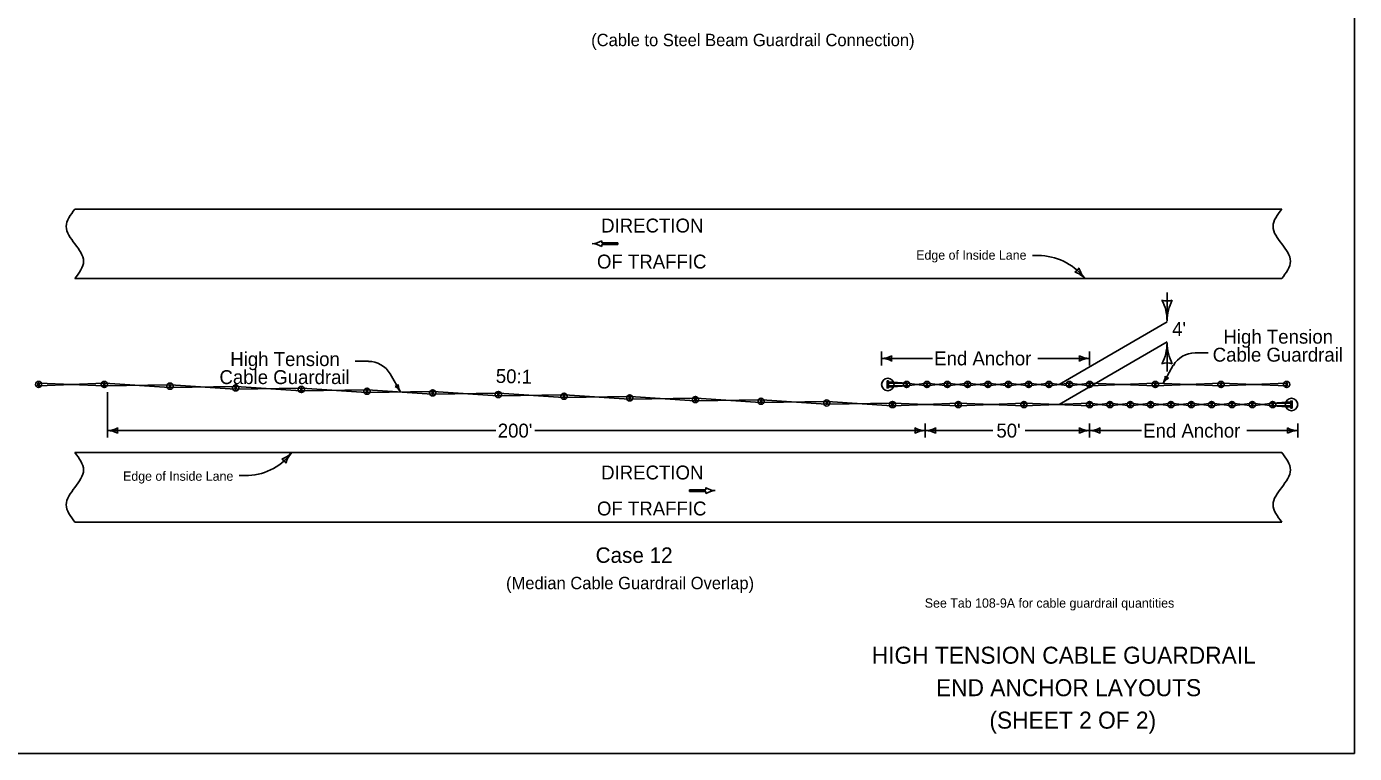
# Model space of a CAD drawing. Extents: x 10133 to 81668, y 7924 to 11018.
# Drawn here: x 15149 to 16868, y 7924 to 8864 of the extents above; entities that cross this region are included whole.
import ezdxf

# ---------------------------------------------------------------- set-up
doc = ezdxf.new("R2010")
doc.units = 0
for name, color, linetype in [('dsnCellElements', 7, 'Continuous'), ('dsnShadingGranular', 7, 'Continuous'), ('DsnShtRevisedText', 7, 'Continuous'), ('dsnStdDimension', 7, 'Continuous'), ('dsnTextTabulation', 7, 'Continuous'), ('Level 8', 7, 'Continuous'), ('SheetBorder', 7, 'Continuous')]:
    doc.layers.add(name, color=color, linetype=linetype)

msp = doc.modelspace()

# ---------------------------------------------------------------- linework, layer by layer
at = {"layer": 'dsnCellElements'}
for p, q in [((16263.5, 8404.9), (16288.6, 8403.1)), ((15248.7, 8403.1), (15165, 8399.7)), ((15248.7, 8399.7), (15165, 8403.1)), ((15250, 8399.7), (15333.7, 8400.9)), ((15250.1, 8403), (15333.7, 8397.5)), ((15335.1, 8397.5), (15418.8, 8398.7)), ((15335.2, 8400.9), (15418.7, 8395.4)), ((15420.1, 8395.3), (15503.8, 8396.6)), ((15420.2, 8398.7), (15503.7, 8393.2)), ((15505.1, 8393.2), (15588.8, 8394.4)), ((15505.2, 8396.5), (15588.7, 8391)), ((15590.1, 8391), (15673.8, 8392.2)), ((15590.2, 8394.4), (15673.8, 8388.9)), ((15675.2, 8392.2), (15758.8, 8386.7)), ((15675.2, 8388.8), (15758.9, 8390.1)), ((15760.2, 8386.7), (15843.9, 8387.9)), ((15760.3, 8390), (15843.8, 8384.5)), ((15845.3, 8387.9), (15928.8, 8382.4)), ((16263.5, 8403.1), (16287.2, 8403.1)), ((16263.5, 8399.7), (16287.2, 8399.7)), ((16263.5, 8397.9), (16288.6, 8399.7)), ((16288.6, 8399.7), (16313.5, 8403.1)), ((16288.6, 8403.1), (16313.5, 8399.7)), ((16314.9, 8399.7), (16339.8, 8403.1)), ((16314.9, 8403.1), (16339.8, 8399.7)), ((16341.3, 8399.7), (16366.1, 8403.1)), ((16341.3, 8403.1), (16366.1, 8399.7)), ((16367.5, 8399.7), (16392.5, 8403.1)), ((16367.5, 8403.1), (16392.5, 8399.7)), ((16393.9, 8399.7), (16418.8, 8403.1)), ((16393.9, 8403.1), (16418.8, 8399.7)), ((16420.2, 8399.7), (16445.1, 8403.1)), ((16420.2, 8403.1), (16445.1, 8399.7)), ((16446.6, 8403.1), (16471.4, 8399.7)), ((16446.6, 8399.7), (16471.4, 8403.1)), ((16472.8, 8399.7), (16497.8, 8403.1)), ((16472.8, 8403.1), (16497.8, 8399.7)), ((16499.2, 8399.7), (16524.1, 8403.1)), ((16499.2, 8403.1), (16524.1, 8399.7)), ((16609.1, 8403.1), (16525.5, 8399.7)), ((16609.1, 8399.7), (16525.5, 8403.1)), ((16694.2, 8403.1), (16610.5, 8399.7)), ((16694.2, 8399.7), (16610.5, 8403.1)), ((16779.2, 8403.1), (16695.6, 8399.7)), ((16779.2, 8399.7), (16695.6, 8403.1)), ((15845.2, 8384.5), (15928.9, 8385.7)), ((15930.2, 8382.3), (16013.9, 8383.6)), ((15930.3, 8385.7), (16013.9, 8380.2)), ((16015.3, 8383.5), (16098.9, 8378)), ((16015.3, 8380.2), (16099, 8381.4)), ((16100.3, 8378), (16184, 8379.2)), ((16100.4, 8381.4), (16183.9, 8375.9)), ((16185.3, 8375.8), (16269, 8377.1)), ((16185.4, 8379.2), (16268.9, 8373.7)), ((16270.3, 8373.7), (16354, 8377.1)), ((16270.3, 8377.1), (16354, 8373.7)), ((16355.4, 8373.7), (16439, 8377.1)), ((16355.4, 8377.1), (16439, 8373.7)), ((16440.4, 8373.7), (16524.1, 8377.1)), ((16440.4, 8377.1), (16524.1, 8373.7)), ((16550.3, 8377.1), (16525.5, 8373.7)), ((16550.3, 8373.7), (16525.5, 8377.1)), ((16576.7, 8377.1), (16551.8, 8373.7)), ((16576.7, 8373.7), (16551.8, 8377.1)), ((16603, 8373.7), (16578.1, 8377.1)), ((16603, 8377.1), (16578.1, 8373.7)), ((16629.3, 8377.1), (16604.4, 8373.7)), ((16629.3, 8373.7), (16604.4, 8377.1)), ((16655.6, 8377.1), (16630.7, 8373.7)), ((16655.6, 8373.7), (16630.7, 8377.1)), ((16682, 8377.1), (16657, 8373.7)), ((16682, 8373.7), (16657, 8377.1)), ((16708.3, 8377.1), (16683.4, 8373.7)), ((16708.3, 8373.7), (16683.4, 8377.1)), ((16734.6, 8377.1), (16709.7, 8373.7)), ((16734.6, 8373.7), (16709.7, 8377.1)), ((16760.9, 8377.1), (16736, 8373.7)), ((16760.9, 8373.7), (16736, 8377.1)), ((16786.1, 8378.9), (16760.9, 8377.1)), ((16786.1, 8372), (16760.9, 8373.7)), ((16786.1, 8377.1), (16762.3, 8377.1)), ((16786.1, 8373.7), (16762.3, 8373.7))]:
    msp.add_line(p, q, dxfattribs=at)
for points in [[(16262.6, 8405.9), (16262.6, 8396.9), (16264.4, 8396.9), (16264.4, 8405.9)], [(15165, 8399.7), (15165, 8403.1), (15163.6, 8403.1), (15163.6, 8399.7)], [(15248.7, 8403.1), (15248.6, 8399.7), (15250, 8399.7), (15250.1, 8403)], [(15250.1, 8399.7), (15250.1, 8403.1), (15248.7, 8403.1), (15248.7, 8399.7)], [(15333.7, 8400.9), (15333.7, 8397.5), (15335.1, 8397.5), (15335.2, 8400.9)], [(15333.7, 8400.9), (15333.7, 8397.5), (15335.1, 8397.5), (15335.2, 8400.9)], [(15418.8, 8398.7), (15418.7, 8395.4), (15420.1, 8395.3), (15420.2, 8398.7)], [(15418.8, 8398.7), (15418.7, 8395.4), (15420.1, 8395.3), (15420.2, 8398.7)], [(15503.8, 8396.6), (15503.7, 8393.2), (15505.1, 8393.2), (15505.2, 8396.5)], [(15503.8, 8396.6), (15503.7, 8393.2), (15505.1, 8393.2), (15505.2, 8396.5)], [(15588.8, 8394.4), (15588.7, 8391), (15590.1, 8391), (15590.2, 8394.4)], [(15588.8, 8394.4), (15588.7, 8391), (15590.1, 8391), (15590.2, 8394.4)], [(15673.8, 8392.2), (15673.8, 8388.9), (15675.2, 8388.8), (15675.2, 8392.2)], [(15673.8, 8392.2), (15673.8, 8388.9), (15675.2, 8388.8), (15675.2, 8392.2)], [(15758.9, 8390.1), (15758.8, 8386.7), (15760.2, 8386.7), (15760.3, 8390)], [(15758.9, 8390.1), (15758.8, 8386.7), (15760.2, 8386.7), (15760.3, 8390)], [(15843.9, 8387.9), (15843.8, 8384.5), (15845.2, 8384.5), (15845.3, 8387.9)], [(15843.9, 8387.9), (15843.8, 8384.5), (15845.2, 8384.5), (15845.3, 8387.9)], [(16287.2, 8403.1), (16287.2, 8399.7), (16288.6, 8399.7), (16288.6, 8403.1)], [(16313.5, 8403.1), (16313.5, 8399.7), (16314.9, 8399.7), (16314.9, 8403.1)], [(16339.9, 8403.1), (16339.9, 8399.7), (16341.3, 8399.7), (16341.3, 8403.1)], [(16366.1, 8403.1), (16366.1, 8399.7), (16367.5, 8399.7), (16367.5, 8403.1)], [(16392.5, 8403.1), (16392.5, 8399.7), (16393.9, 8399.7), (16393.9, 8403.1)], [(16418.8, 8403.1), (16418.8, 8399.7), (16420.2, 8399.7), (16420.2, 8403.1)], [(16445.1, 8403.1), (16445.1, 8399.7), (16446.6, 8399.7), (16446.6, 8403.1)], [(16471.4, 8403.1), (16471.4, 8399.7), (16472.8, 8399.7), (16472.8, 8403.1)], [(16497.8, 8403.1), (16497.8, 8399.7), (16499.2, 8399.7), (16499.2, 8403.1)], [(16524.1, 8403.1), (16524.1, 8399.7), (16525.5, 8399.7), (16525.5, 8403.1)], [(16524.1, 8403.1), (16524.1, 8399.7), (16525.5, 8399.7), (16525.5, 8403.1)], [(16525.5, 8399.7), (16525.5, 8403.1), (16524.1, 8403.1), (16524.1, 8399.7)], [(16610.5, 8399.7), (16610.5, 8403.1), (16609.1, 8403.1), (16609.1, 8399.7)], [(16610.5, 8399.7), (16610.5, 8403.1), (16609.1, 8403.1), (16609.1, 8399.7)], [(16695.6, 8399.7), (16695.6, 8403.1), (16694.2, 8403.1), (16694.2, 8399.7)], [(16695.6, 8399.7), (16695.6, 8403.1), (16694.2, 8403.1), (16694.2, 8399.7)], [(16780.6, 8399.7), (16780.6, 8403.1), (16779.2, 8403.1), (16779.2, 8399.7)], [(15928.9, 8385.7), (15928.8, 8382.4), (15930.2, 8382.3), (15930.3, 8385.7)], [(15928.9, 8385.7), (15928.8, 8382.4), (15930.2, 8382.3), (15930.3, 8385.7)], [(16013.9, 8383.6), (16013.9, 8380.2), (16015.3, 8380.2), (16015.3, 8383.5)], [(16013.9, 8383.6), (16013.9, 8380.2), (16015.3, 8380.2), (16015.3, 8383.5)], [(16099, 8381.4), (16098.9, 8378), (16100.3, 8378), (16100.4, 8381.4)], [(16099, 8381.4), (16098.9, 8378), (16100.3, 8378), (16100.4, 8381.4)], [(16184, 8379.2), (16183.9, 8375.9), (16185.3, 8375.8), (16185.4, 8379.2)], [(16184, 8379.2), (16183.9, 8375.9), (16185.3, 8375.8), (16185.4, 8379.2)], [(16268.9, 8377.1), (16268.9, 8373.7), (16270.3, 8373.7), (16270.3, 8377.1)], [(16269, 8377.1), (16268.9, 8373.7), (16270.3, 8373.7), (16270.4, 8377)], [(16354, 8377.1), (16354, 8373.7), (16355.4, 8373.7), (16355.4, 8377.1)], [(16354, 8377.1), (16354, 8373.7), (16355.4, 8373.7), (16355.4, 8377.1)], [(16439, 8377.1), (16439, 8373.7), (16440.4, 8373.7), (16440.4, 8377.1)], [(16439, 8377.1), (16439, 8373.7), (16440.4, 8373.7), (16440.4, 8377.1)], [(16524.1, 8377.1), (16524.1, 8373.7), (16525.5, 8373.7), (16525.5, 8377.1)], [(16525.5, 8373.7), (16525.5, 8377.1), (16524.1, 8377.1), (16524.1, 8373.7)], [(16525.5, 8373.7), (16525.5, 8377.1), (16524.1, 8377.1), (16524.1, 8373.7)], [(16551.8, 8373.7), (16551.8, 8377.1), (16550.3, 8377.1), (16550.3, 8373.7)], [(16578.1, 8373.7), (16578.1, 8377.1), (16576.7, 8377.1), (16576.7, 8373.7)], [(16604.4, 8373.7), (16604.4, 8377.1), (16603, 8377.1), (16603, 8373.7)], [(16630.7, 8373.7), (16630.7, 8377.1), (16629.3, 8377.1), (16629.3, 8373.7)], [(16657, 8373.7), (16657, 8377.1), (16655.6, 8377.1), (16655.6, 8373.7)], [(16683.4, 8373.7), (16683.4, 8377.1), (16682, 8377.1), (16682, 8373.7)], [(16709.7, 8373.7), (16709.7, 8377.1), (16708.3, 8377.1), (16708.3, 8373.7)], [(16736, 8373.7), (16736, 8377.1), (16734.6, 8377.1), (16734.6, 8373.7)], [(16762.3, 8373.7), (16762.3, 8377.1), (16760.9, 8377.1), (16760.9, 8373.7)], [(16787, 8370.9), (16787, 8379.9), (16785.1, 8379.9), (16785.1, 8370.9)]]:
    msp.add_lwpolyline(points, close=True, dxfattribs=at)
for centre, radius in [((15164.3, 8401.4), 3.99), ((15249.4, 8401.4), 3.99), ((15249.4, 8401.4), 3.99), ((16263.5, 8401.4), 8.1), ((16287.9, 8401.4), 3.99), ((16314.2, 8401.4), 3.99), ((16340.6, 8401.4), 3.99), ((16366.8, 8401.4), 3.99), ((16393.2, 8401.4), 3.99), ((16419.5, 8401.4), 3.99), ((16445.9, 8401.4), 3.99), ((16472.1, 8401.4), 3.99), ((16498.5, 8401.4), 3.99), ((16524.8, 8401.4), 3.99), ((16524.8, 8401.4), 3.99), ((16609.8, 8401.4), 3.99), ((16609.8, 8401.4), 3.99), ((16694.9, 8401.4), 3.99), ((16694.9, 8401.4), 3.99), ((16779.9, 8401.4), 3.99), ((15334.4, 8399.2), 3.99), ((15334.4, 8399.2), 3.99), ((15419.4, 8397), 3.99), ((15419.4, 8397), 3.99), ((15504.5, 8394.9), 3.99), ((15504.5, 8394.9), 3.99), ((15589.5, 8392.7), 3.99), ((15589.5, 8392.7), 3.99), ((15674.5, 8390.5), 3.99), ((15674.5, 8390.5), 3.99), ((15759.5, 8388.4), 3.99), ((15759.5, 8388.4), 3.99), ((15844.5, 8386.2), 3.99), ((15844.5, 8386.2), 3.99), ((15929.6, 8384), 3.99), ((15929.6, 8384), 3.99), ((16014.6, 8381.9), 3.99), ((16014.6, 8381.9), 3.99), ((16099.6, 8379.7), 3.99), ((16099.6, 8379.7), 3.99), ((16184.6, 8377.5), 3.99), ((16184.6, 8377.5), 3.99), ((16269.6, 8375.4), 3.99), ((16269.7, 8375.4), 3.99), ((16354.7, 8375.4), 3.99), ((16354.7, 8375.4), 3.99), ((16439.7, 8375.4), 3.99), ((16439.7, 8375.4), 3.99), ((16524.8, 8375.4), 3.99), ((16524.8, 8375.4), 3.99), ((16551, 8375.4), 3.99), ((16577.4, 8375.4), 3.99), ((16603.7, 8375.4), 3.99), ((16630, 8375.4), 3.99), ((16656.3, 8375.4), 3.99), ((16682.7, 8375.4), 3.99), ((16709, 8375.4), 3.99), ((16735.3, 8375.4), 3.99), ((16761.6, 8375.4), 3.99), ((16786.1, 8375.4), 8.1)]:
    msp.add_circle(centre, radius, dxfattribs=at)
at = {"layer": 'DsnShtRevisedText'}
for p, q in [((15881.1, 8583.6), (15881.1, 8583.6)), ((15893.2, 8587.4), (15893.2, 8584.7)), ((15893.2, 8584.7), (15914.2, 8584.7)), ((15914.2, 8582.4), (15893.2, 8582.4)), ((15893.2, 8582.4), (15893.2, 8579.8)), ((15914.2, 8584.7), (15914.2, 8582.4)), ((16450.8, 8568.2), (16458.3, 8568.2)), ((16625, 8520.5), (16625, 8483.5)), ((16485.3, 8401.4), (16625, 8482.4)), ((16485.3, 8375.4), (16625, 8456.4)), ((16255.4, 8444.1), (16255.4, 8426.1)), ((16524.8, 8444.1), (16524.8, 8426.1)), ((16625, 8455.2), (16625, 8418.2)), ((16661.3, 8442.4), (16678.2, 8442.4)), ((15591.2, 8431.4), (15574.3, 8431.4)), ((16255.4, 8435.1), (16321.4, 8435.1)), ((16524.8, 8435.1), (16457.6, 8435.1)), ((16633.1, 8426.2), (16619.8, 8402.7)), ((15619.4, 8415.2), (15632.7, 8391.7)), ((15253.4, 8391.5), (15253.4, 8332.7)), ((15756.3, 8341.7), (15253.4, 8341.7)), ((16312.1, 8341.7), (15806.5, 8341.7)), ((16312.1, 8350.7), (16312.1, 8332.7)), ((16312.1, 8341.7), (16399.3, 8341.7)), ((16524.8, 8341.7), (16441.4, 8341.7)), ((16524.8, 8332.7), (16524.8, 8350.7)), ((16524.8, 8341.7), (16592, 8341.7)), ((16794.2, 8341.7), (16728.1, 8341.7)), ((16794.2, 8350.7), (16794.2, 8332.7)), ((15424.2, 8283.5), (15431.7, 8283.5)), ((16028, 8267.9), (16028, 8265.2)), ((16028, 8265.2), (16007, 8265.2)), ((16007, 8265.2), (16007, 8262.9)), ((16007, 8262.9), (16028, 8262.9)), ((16028, 8262.9), (16028, 8260.3)), ((16040.1, 8264.1), (16040.1, 8264.1))]:
    msp.add_line(p, q, dxfattribs=at)
for centre, radius, start, end in [((15880.1, 8608.1), 24.6, 272.352, 302.382), ((15880.1, 8559), 24.6, 57.618, 87.648), ((16458.3, 8492), 76.2, 39.0106, 90), ((16500.3, 8558.2), 12.5, 295.2639, 330.7306), ((16495.1, 8516.2), 32.4, 42.9973, 71.0698), ((16542.5, 8560.4), 32.4, 194.9248, 222.9973), ((16661.3, 8409.7), 32.6, 90, 149.7757), ((15591.2, 8398.7), 32.6, 30.2243, 90), ((16255.4, 8463.8), 28.7, 270, 298.0725), ((16255.4, 8406.4), 28.7, 61.9275, 90), ((16279.4, 8435.1), 11.1, 162.2666, 197.7334), ((16500.7, 8435.1), 11.1, 342.2667, 17.7334), ((16524.8, 8463.8), 28.7, 241.9275, 270), ((16524.8, 8406.4), 28.7, 90, 118.0725), ((16602.2, 8413), 20.4, 329.7686, 357.8411), ((16637.4, 8392.4), 20.4, 121.6962, 149.7686), ((16628.4, 8417.5), 7.88, 222.0353, 257.502), ((15624.1, 8406.5), 7.88, 282.498, 317.9647), ((15615.1, 8381.4), 20.4, 30.2314, 58.3038), ((15650.3, 8402), 20.4, 182.1589, 210.2314), ((15253.4, 8370.4), 28.7, 270, 298.0725), ((15253.4, 8313), 28.7, 61.9275, 90), ((15277.5, 8341.7), 11.1, 162.2666, 197.7334), ((16288.1, 8341.7), 11.1, 342.2666, 17.7333), ((16312.1, 8370.4), 28.7, 241.9275, 270), ((16312.1, 8313), 28.7, 90, 118.0725), ((16312.1, 8370.4), 28.7, 270, 298.0725), ((16312.1, 8313), 28.7, 61.9275, 90), ((16336.2, 8341.7), 11.1, 162.2666, 197.7334), ((16500.7, 8341.7), 11.1, 342.2666, 17.7333), ((16524.8, 8370.4), 28.7, 241.9275, 270), ((16524.8, 8313), 28.7, 90, 118.0725), ((16524.8, 8370.4), 28.7, 270, 298.0725), ((16524.8, 8313), 28.7, 61.9275, 90), ((16548.8, 8341.7), 11.1, 162.2666, 197.7334), ((16770.1, 8341.7), 11.1, 342.2667, 17.7334), ((16794.2, 8370.4), 28.7, 241.9275, 270), ((16794.2, 8313), 28.7, 90, 118.0725), ((15431.7, 8359.6), 76.2, 270, 320.9894), ((15468.5, 8335.4), 32.4, 288.9302, 317.0027), ((15473.7, 8293.5), 12.5, 29.2694, 64.7361), ((15515.9, 8291.2), 32.4, 137.0027, 165.0752), ((16041.2, 8288.6), 24.6, 237.618, 267.648), ((16041.2, 8239.5), 24.6, 92.352, 122.382)]:
    msp.add_arc(centre, radius, start, end, dxfattribs=at)
at = {"layer": 'dsnStdDimension'}
for p, q in [((15211.4, 8628.3), (16773.4, 8628.3)), ((15211.4, 8538.3), (16773.4, 8538.3)), ((15211.4, 8313.3), (16773.4, 8313.3)), ((15211.4, 8223.3), (16773.4, 8223.3))]:
    msp.add_line(p, q, dxfattribs=at)
for points in [[(15211.4, 8538.3), (15222.6, 8560.8), (15211.4, 8583.3), (15200.1, 8605.8), (15211.4, 8628.3)], [(16773.4, 8538.3), (16784.7, 8560.8), (16773.4, 8583.3), (16762.2, 8605.8), (16773.4, 8628.3)], [(15211.4, 8313.3), (15222.6, 8290.8), (15211.4, 8268.3), (15200.1, 8245.8), (15211.4, 8223.3)], [(16773.4, 8313.3), (16784.7, 8290.8), (16773.4, 8268.3), (16762.2, 8245.8), (16773.4, 8223.3)]]:
    msp.add_spline(points, degree=3, dxfattribs=at)
at = {"layer": 'dsnTextTabulation'}
for centre, radius, start, end in [((16625, 8531.6), 22.2, 252.2666, 287.7334), ((16567.6, 8483.5), 57.4, 360, 28.0725), ((16682.4, 8483.5), 57.4, 151.9275, 180), ((16567.6, 8455.2), 57.4, 331.9275, 0), ((16682.4, 8455.2), 57.4, 180, 208.0725), ((16625, 8407.1), 22.2, 72.2666, 107.7334)]:
    msp.add_arc(centre, radius, start, end, dxfattribs=at)
at = {"layer": 'SheetBorder'}
msp.add_lwpolyline([(13732.5, 9944), (16867.5, 9944), (16867.5, 7924), (13732.5, 7924)], close=True, dxfattribs=at)

# ---------------------------------------------------------------- texts
at = {"layer": 'dsnShadingGranular'}
for s, p in [('HIGH TENSION CABLE GUARDRAIL', (16242.8, 8040.1)), ('END ANCHOR LAYOUTS', (16325.9, 7998.1)), ('(SHEET 2 OF 2)', (16395.1, 7956.1))]:
    msp.add_text(s, height=22, dxfattribs=at).set_placement(p)
at = {"layer": 'DsnShtRevisedText'}
for s, height, p in [('DIRECTION', 18, (15892.5, 8598)), ('OF TRAFFIC', 18, (15887.1, 8551.4)), ('Edge of Inside Lane', 12, (16300.3, 8562.8)), ('High Tension', 18, (16698, 8454.2)), ('High Tension', 18, (15412.5, 8425.2)), ('End Anchor', 18, (16323.6, 8426.1)), ('Cable Guardrail', 18, (16684.1, 8430.9)), ('Cable Guardrail', 18, (15398.5, 8401.9)), ("200'", 18, (15758.7, 8332.7)), ("50'", 18, (16404.1, 8332.7)), ('End Anchor', 18, (16594.1, 8332.7)), ('Edge of Inside Lane', 12, (15273.7, 8276.8)), ('DIRECTION', 18, (15892.5, 8278.5)), ('OF TRAFFIC', 18, (15887.1, 8231.9))]:
    msp.add_text(s, height=height, dxfattribs=at).set_placement(p)
msp.add_text('50:1', height=18, rotation=358.524, dxfattribs=at).set_placement((15756, 8403.5))
at = {"layer": 'dsnTextTabulation'}
msp.add_text("4'", height=18, dxfattribs=at).set_placement((16631.5, 8464.1))
at = {"layer": 'Level 8'}
for s, height, p in [('(Cable to Steel Beam Guardrail Connection)', 16, (15879.6, 8839.1)), ('Case 12', 20, (15885.4, 8170.6)), ('(Median Cable Guardrail Overlap)', 16, (15769.4, 8136.5)), ('See Tab 108-9A for cable guardrail quantities', 12, (16311.4, 8112.6))]:
    msp.add_text(s, height=height, dxfattribs=at).set_placement(p)

doc.saveas('drawing.dxf')
